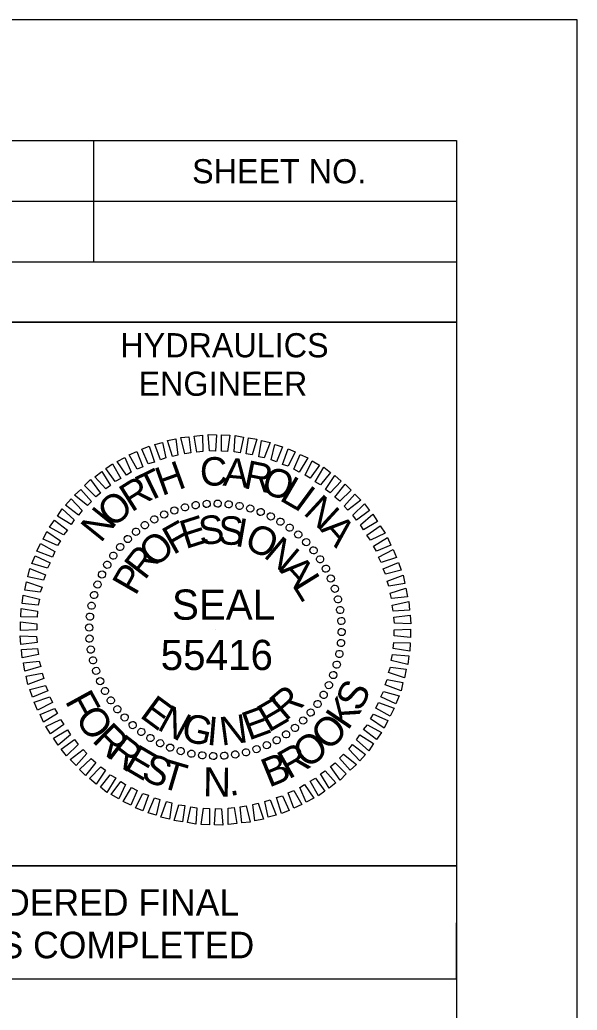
# Model space of a CAD drawing. Extents: x 573078 to 573156.2, y -55225.7 to -55195.8.
# Drawn here: x 573109.707 to 573112.014, y -55203.398 to -55199.298 of the extents above; entities that cross this region are included whole.
import ezdxf

# ---------------------------------------------------------------- set-up
doc = ezdxf.new("R2010")
doc.units = 0
for name, color, linetype in [('Prop Dimension', 7, 'Continuous'), ('Scratch_Level_0', 7, 'Continuous'), ('Scratch_Level_1', 7, 'Continuous'), ('Sheet Plan CELL', 7, 'Continuous'), ('Sheet Plot Border Inside CELL', 7, 'Continuous'), ('Sheet Sticker Exception Certification CELL', 7, 'Continuous')]:
    doc.layers.add(name, color=color, linetype=linetype)

msp = doc.modelspace()

# ---------------------------------------------------------------- linework, layer by layer
at = {"layer": 'Prop Dimension'}
for p, q in [((573110.39, -55201.316), (573110.39, -55201.316)), ((573110.4359, -55201.3077), (573110.4359, -55201.3077)), ((573110.4805, -55201.3015), (573110.4805, -55201.3015)), ((573110.5263, -55201.3005), (573110.5263, -55201.3005)), ((573110.5722, -55201.3035), (573110.5722, -55201.3035)), ((573110.617, -55201.3109), (573110.617, -55201.3109)), ((573110.6608, -55201.3202), (573110.6608, -55201.3202)), ((573110.3046, -55201.3452), (573110.3046, -55201.3452)), ((573110.3463, -55201.3285), (573110.3463, -55201.3285)), ((573110.7045, -55201.3348), (573110.7045, -55201.3348)), ((573110.7462, -55201.3535), (573110.7462, -55201.3535)), ((573110.2243, -55201.3901), (573110.2243, -55201.3901)), ((573110.2639, -55201.366), (573110.2639, -55201.366)), ((573110.7867, -55201.3744), (573110.7867, -55201.3744)), ((573110.8242, -55201.4005), (573110.8242, -55201.4005)), ((573110.188, -55201.416), (573110.188, -55201.416)), ((573110.8607, -55201.4285), (573110.8607, -55201.4285)), ((573110.1223, -55201.4796), (573110.1223, -55201.4796)), ((573110.1535, -55201.4473), (573110.1535, -55201.4473)), ((573110.8929, -55201.4597), (573110.8929, -55201.4597)), ((573110.0943, -55201.516), (573110.0943, -55201.516)), ((573110.9241, -55201.4942), (573110.9241, -55201.4942)), ((573110.0681, -55201.5535), (573110.0681, -55201.5535)), ((573110.9503, -55201.5306), (573110.9503, -55201.5306)), ((573110.0473, -55201.5942), (573110.0473, -55201.5942)), ((573110.9741, -55201.5701), (573110.9741, -55201.5701)), ((573110.0286, -55201.6359), (573110.0286, -55201.6359)), ((573110.995, -55201.6109), (573110.995, -55201.6109)), ((573110.014, -55201.6796), (573110.014, -55201.6796)), ((573111.0116, -55201.6525), (573111.0116, -55201.6525)), ((573110.0047, -55201.7233), (573110.0047, -55201.7233)), ((573111.0241, -55201.6963), (573111.0241, -55201.6963)), ((573109.9973, -55201.768), (573109.9973, -55201.768)), ((573111.0324, -55201.7421), (573111.0324, -55201.7421)), ((573111.0387, -55201.7867), (573111.0387, -55201.7867)), ((573109.9943, -55201.8138), (573109.9943, -55201.8138)), ((573111.0398, -55201.8326), (573111.0398, -55201.8326)), ((573109.9952, -55201.8596), (573109.9952, -55201.8596)), ((573111.0366, -55201.8784), (573111.0366, -55201.8784)), ((573110.0015, -55201.9045), (573110.0015, -55201.9045)), ((573111.0294, -55201.9233), (573111.0294, -55201.9233)), ((573110.0098, -55201.9504), (573110.0098, -55201.9504)), ((573111.0199, -55201.967), (573111.0199, -55201.967)), ((573110.0223, -55201.9941), (573110.0223, -55201.9941)), ((573111.0054, -55202.0108), (573111.0054, -55202.0108)), ((573110.039, -55202.0357), (573110.039, -55202.0357)), ((573110.9866, -55202.0524), (573110.9866, -55202.0524)), ((573110.0598, -55202.0762), (573110.0598, -55202.0762)), ((573110.9658, -55202.0929), (573110.9658, -55202.0929)), ((573110.0839, -55202.1158), (573110.0839, -55202.1158)), ((573110.9399, -55202.1304), (573110.9399, -55202.1304)), ((573110.1098, -55202.1524), (573110.1098, -55202.1524)), ((573110.9116, -55202.167), (573110.9116, -55202.167)), ((573110.141, -55202.1866), (573110.141, -55202.1866)), ((573110.1734, -55202.2179), (573110.1734, -55202.2179)), ((573110.8804, -55202.1991), (573110.8804, -55202.1991)), ((573110.2098, -55202.2461), (573110.2098, -55202.2461)), ((573110.8096, -55202.2565), (573110.8096, -55202.2565)), ((573110.8462, -55202.2304), (573110.8462, -55202.2304)), ((573110.2472, -55202.272), (573110.2472, -55202.272)), ((573110.288, -55202.2929), (573110.288, -55202.2929)), ((573110.7295, -55202.3012), (573110.7295, -55202.3012)), ((573110.77, -55202.2804), (573110.77, -55202.2804)), ((573110.3296, -55202.3116), (573110.3296, -55202.3116)), ((573110.3734, -55202.3262), (573110.3734, -55202.3262)), ((573110.4171, -55202.3357), (573110.4171, -55202.3357)), ((573110.4618, -55202.3428), (573110.4618, -55202.3428)), ((573110.5534, -55202.3449), (573110.5534, -55202.3449)), ((573110.5983, -55202.3387), (573110.5983, -55202.3387)), ((573110.6441, -55202.3303), (573110.6441, -55202.3303)), ((573110.6879, -55202.3178), (573110.6879, -55202.3178)), ((573110.5076, -55202.3461), (573110.5076, -55202.3461))]:
    msp.add_line(p, q, dxfattribs=at)
for points in [[(573110.34, -55201.1057), (573110.3181, -55201.0402), (573110.3535, -55201.0328), (573110.3618, -55201.1006)], [(573110.39, -55201.0943), (573110.3734, -55201.0277), (573110.4076, -55201.0245), (573110.415, -55201.0911)], [(573110.44, -55201.0881), (573110.4284, -55201.0214), (573110.4639, -55201.0173), (573110.465, -55201.0849)], [(573110.4921, -55201.0828), (573110.4868, -55201.0152), (573110.5212, -55201.0161), (573110.5171, -55201.0839)], [(573110.5421, -55201.0839), (573110.5421, -55201.0161), (573110.5763, -55201.0173), (573110.5671, -55201.0848)], [(573110.5941, -55201.0869), (573110.5983, -55201.0194), (573110.6326, -55201.0256), (573110.6191, -55201.0911)], [(573110.6441, -55201.0953), (573110.6534, -55201.0286), (573110.6879, -55201.0339), (573110.6691, -55201.0985)], [(573110.2389, -55201.136), (573110.2118, -55201.0756), (573110.2431, -55201.0631), (573110.2651, -55201.1297)], [(573110.2901, -55201.1193), (573110.266, -55201.0568), (573110.2984, -55201.0474), (573110.3118, -55201.1119)], [(573110.6971, -55201.1068), (573110.7075, -55201.039), (573110.7429, -55201.0474), (573110.7191, -55201.1119)], [(573110.7471, -55201.1203), (573110.7628, -55201.0557), (573110.795, -55201.0661), (573110.7691, -55201.1277)], [(573110.7941, -55201.139), (573110.8179, -55201.0735), (573110.8471, -55201.086), (573110.8179, -55201.1464)], [(573110.1484, -55201.1827), (573110.1098, -55201.1265), (573110.1422, -55201.1098), (573110.1681, -55201.1702)], [(573110.1931, -55201.1577), (573110.1598, -55201.0994), (573110.1922, -55201.0849), (573110.216, -55201.1485)], [(573110.8408, -55201.1589), (573110.867, -55201.0974), (573110.8991, -55201.1119), (573110.8637, -55201.1702)], [(573110.1026, -55201.2089), (573110.064, -55201.1557), (573110.091, -55201.136), (573110.1255, -55201.1964)], [(573110.8887, -55201.1827), (573110.917, -55201.1235), (573110.9482, -55201.1411), (573110.9086, -55201.1952)], [(573110.9295, -55201.211), (573110.9658, -55201.1506), (573110.9929, -55201.1723), (573110.9524, -55201.2235)], [(573110.063, -55201.2401), (573110.0181, -55201.1901), (573110.0464, -55201.1682), (573110.0827, -55201.2265)], [(573110.972, -55201.2422), (573111.0107, -55201.1848), (573111.0378, -55201.2077), (573110.9919, -55201.2568)], [(573110.0214, -55201.2723), (573109.9756, -55201.2265), (573110.0006, -55201.2015), (573110.0411, -55201.2577)], [(573111.0116, -55201.2744), (573111.0544, -55201.2202), (573111.0794, -55201.2452), (573111.0315, -55201.2901)], [(573109.9869, -55201.3089), (573109.9339, -55201.2661), (573109.9598, -55201.2422), (573110.0036, -55201.2922)], [(573111.0491, -55201.3109), (573111.094, -55201.2619), (573111.119, -55201.2869), (573111.0648, -55201.3276)], [(573109.9506, -55201.3484), (573109.8964, -55201.3077), (573109.9193, -55201.2806), (573109.9651, -55201.3297)], [(573111.0857, -55201.3484), (573111.1336, -55201.3015), (573111.1553, -55201.3297), (573111.1003, -55201.3693)], [(573109.9193, -55201.388), (573109.8631, -55201.3526), (573109.8828, -55201.3223), (573109.9328, -55201.3681)], [(573111.1169, -55201.3889), (573111.1678, -55201.3452), (573111.1877, -55201.3755), (573111.1294, -55201.4088)], [(573109.8881, -55201.4297), (573109.8298, -55201.3984), (573109.8506, -55201.3693), (573109.9047, -55201.4109)], [(573111.144, -55201.4317), (573111.1991, -55201.3922), (573111.219, -55201.4234), (573111.1586, -55201.4526)], [(573109.8631, -55201.4743), (573109.8036, -55201.4484), (573109.8194, -55201.416), (573109.8756, -55201.4547)], [(573111.1711, -55201.4776), (573111.2294, -55201.441), (573111.2428, -55201.4734), (573111.1836, -55201.4972)], [(573109.8423, -55201.5222), (573109.7777, -55201.4984), (573109.7932, -55201.466), (573109.8527, -55201.4993)], [(573109.8214, -55201.5681), (573109.7569, -55201.5493), (573109.7703, -55201.5171), (573109.8328, -55201.5463)], [(573111.1919, -55201.5222), (573111.2532, -55201.491), (573111.2669, -55201.5243), (573111.2023, -55201.5451)], [(573111.2106, -55201.5713), (573111.274, -55201.5442), (573111.2856, -55201.5764), (573111.221, -55201.593)], [(573109.8057, -55201.618), (573109.7411, -55201.6046), (573109.7485, -55201.5701), (573109.814, -55201.5963)], [(573111.2273, -55201.6213), (573111.2939, -55201.5972), (573111.3002, -55201.6317), (573111.2345, -55201.643)], [(573109.7923, -55201.668), (573109.7277, -55201.6597), (573109.7349, -55201.6243), (573109.8006, -55201.6463)], [(573109.784, -55201.7213), (573109.7173, -55201.715), (573109.7215, -55201.6796), (573109.789, -55201.6963)], [(573111.2398, -55201.6713), (573111.3053, -55201.6514), (573111.3115, -55201.6868), (573111.246, -55201.693)], [(573111.249, -55201.7212), (573111.3169, -55201.7067), (573111.3199, -55201.7421), (573111.2532, -55201.7462)], [(573109.7786, -55201.7712), (573109.7111, -55201.7692), (573109.7131, -55201.7347), (573109.7807, -55201.7462)], [(573111.2553, -55201.7712), (573111.3231, -55201.7629), (573111.3252, -55201.7983), (573111.2574, -55201.7962)], [(573109.7777, -55201.8233), (573109.7099, -55201.8263), (573109.7099, -55201.7909), (573109.7777, -55201.7983)], [(573109.7786, -55201.8754), (573109.7111, -55201.8837), (573109.709, -55201.8483), (573109.7765, -55201.8504)], [(573111.2565, -55201.8233), (573111.324, -55201.8201), (573111.324, -55201.8555), (573111.2565, -55201.8483)], [(573111.2553, -55201.8754), (573111.3231, -55201.8775), (573111.321, -55201.9117), (573111.2532, -55201.9004)], [(573109.7849, -55201.9254), (573109.7173, -55201.9399), (573109.7141, -55201.9045), (573109.7807, -55201.9004)], [(573111.2502, -55201.9254), (573111.3169, -55201.9316), (573111.3127, -55201.967), (573111.2449, -55201.9504)], [(573109.7944, -55201.9753), (573109.7286, -55201.995), (573109.7224, -55201.9596), (573109.7881, -55201.9534)], [(573109.8069, -55202.0253), (573109.7402, -55202.0492), (573109.734, -55202.0149), (573109.7995, -55202.0033)], [(573111.2419, -55201.9784), (573111.3064, -55201.9867), (573111.299, -55202.0221), (573111.2335, -55202.0003)], [(573109.8235, -55202.0753), (573109.7599, -55202.1024), (573109.7485, -55202.07), (573109.8131, -55202.0533)], [(573111.2282, -55202.0283), (573111.2928, -55202.042), (573111.2856, -55202.0762), (573111.2199, -55202.0503)], [(573111.2127, -55202.0783), (573111.2773, -55202.0971), (573111.2636, -55202.1295), (573111.2011, -55202.1003)], [(573109.8423, -55202.1241), (573109.7807, -55202.1554), (573109.7673, -55202.1221), (573109.8319, -55202.1012)], [(573111.1919, -55202.1241), (573111.2565, -55202.1482), (573111.2407, -55202.1804), (573111.1815, -55202.1471)], [(573109.8631, -55202.169), (573109.8048, -55202.2054), (573109.7911, -55202.1732), (573109.8506, -55202.1491)], [(573111.1711, -55202.172), (573111.2303, -55202.1982), (573111.2148, -55202.2304), (573111.1586, -55202.192)], [(573109.8902, -55202.2149), (573109.8349, -55202.2544), (573109.8152, -55202.2232), (573109.8756, -55202.194)], [(573111.1461, -55202.2169), (573111.2044, -55202.2482), (573111.1836, -55202.2773), (573111.1294, -55202.2357)], [(573109.9172, -55202.2574), (573109.8661, -55202.3012), (573109.8464, -55202.2711), (573109.9047, -55202.2378)], [(573111.1148, -55202.2586), (573111.1711, -55202.294), (573111.1512, -55202.3241), (573111.1012, -55202.2783)], [(573109.9485, -55202.2982), (573109.9006, -55202.3449), (573109.8786, -55202.3169), (573109.9339, -55202.2773)], [(573111.0836, -55202.2982), (573111.1377, -55202.3387), (573111.1148, -55202.3657), (573111.069, -55202.3169)], [(573109.9848, -55202.3357), (573109.9402, -55202.3845), (573109.9152, -55202.3595), (573109.9693, -55202.319)], [(573111.047, -55202.3377), (573111.1003, -55202.3803), (573111.0741, -55202.4044), (573111.0304, -55202.3544)], [(573110.0223, -55202.372), (573109.9797, -55202.4261), (573109.9547, -55202.4012), (573110.0026, -55202.3565)], [(573111.0128, -55202.3741), (573111.0586, -55202.4199), (573111.0336, -55202.4449), (573110.9929, -55202.3887)], [(573110.0619, -55202.4044), (573110.0235, -55202.4616), (573109.9964, -55202.4386), (573110.0422, -55202.3898)], [(573110.1047, -55202.4356), (573110.0681, -55202.496), (573110.0411, -55202.474), (573110.0818, -55202.4231)], [(573110.9711, -55202.4065), (573111.0158, -55202.4565), (573110.9878, -55202.4782), (573110.9512, -55202.4199)], [(573110.1452, -55202.4636), (573110.1172, -55202.5231), (573110.0859, -55202.5053), (573110.1255, -55202.4511)], [(573110.8857, -55202.4636), (573110.9241, -55202.5199), (573110.892, -55202.5365), (573110.8658, -55202.4761)], [(573110.9315, -55202.4377), (573110.97, -55202.4907), (573110.9429, -55202.5106), (573110.9086, -55202.4502)], [(573110.1931, -55202.4877), (573110.1672, -55202.549), (573110.1348, -55202.5345), (573110.1702, -55202.4761)], [(573110.2401, -55202.5074), (573110.216, -55202.5731), (573110.1868, -55202.5606), (573110.216, -55202.5002)], [(573110.8408, -55202.4886), (573110.8742, -55202.5469), (573110.842, -55202.5615), (573110.8179, -55202.4981)], [(573110.2868, -55202.5261), (573110.2713, -55202.5907), (573110.2389, -55202.5803), (573110.2651, -55202.5189)], [(573110.3368, -55202.5398), (573110.3264, -55202.6073), (573110.291, -55202.599), (573110.3151, -55202.5345)], [(573110.39, -55202.5511), (573110.3805, -55202.6178), (573110.3463, -55202.6127), (573110.365, -55202.5481)], [(573110.6941, -55202.5407), (573110.7159, -55202.6064), (573110.6805, -55202.6136), (573110.6721, -55202.546)], [(573110.7441, -55202.5273), (573110.7679, -55202.5898), (573110.7358, -55202.599), (573110.7221, -55202.5344)], [(573110.795, -55202.5106), (573110.8221, -55202.571), (573110.7908, -55202.5835), (573110.7691, -55202.5169)], [(573110.44, -55202.5594), (573110.4359, -55202.6272), (573110.4014, -55202.621), (573110.415, -55202.5553)], [(573110.4921, -55202.5627), (573110.4921, -55202.6303), (573110.4576, -55202.6293), (573110.4671, -55202.5615)], [(573110.5421, -55202.5636), (573110.5472, -55202.6314), (573110.5129, -55202.6303), (573110.5171, -55202.5627)], [(573110.5941, -55202.5585), (573110.6055, -55202.6252), (573110.5701, -55202.6293), (573110.5691, -55202.5615)], [(573110.6441, -55202.5523), (573110.6608, -55202.6189), (573110.6263, -55202.6219), (573110.6191, -55202.5553)]]:
    msp.add_lwpolyline(points, close=True, dxfattribs=at)
for centre, major_axis in [((573110.347, -55201.3293), (-0.0049, 0.0142)), ((573110.3907, -55201.3164), (-0.0036, 0.0146)), ((573110.4354, -55201.3073), (-0.0023, 0.0148)), ((573110.4807, -55201.3022), (-0.001, 0.015)), ((573110.5262, -55201.301), (0.0003, 0.015)), ((573110.5717, -55201.3037), (0.0016, 0.0149)), ((573110.6168, -55201.3105), (0.0029, 0.0147)), ((573110.6611, -55201.3211), (0.0041, 0.0144)), ((573110.7043, -55201.3356), (0.0054, 0.014)), ((573110.2638, -55201.3664), (-0.0073, 0.0131)), ((573110.3046, -55201.346), (-0.0061, 0.0137)), ((573110.7461, -55201.3538), (0.0066, 0.0135)), ((573110.7861, -55201.3755), (0.0077, 0.0129)), ((573110.1884, -55201.4173), (-0.0094, 0.0117)), ((573110.225, -55201.3902), (-0.0084, 0.0124)), ((573110.8241, -55201.4006), (0.0088, 0.0121)), ((573110.1542, -55201.4475), (-0.0104, 0.0108)), ((573110.8598, -55201.429), (0.0098, 0.0113)), ((573110.1229, -55201.4805), (-0.0113, 0.0098)), ((573110.8928, -55201.4604), (0.0108, 0.0104)), ((573110.923, -55201.4945), (0.0117, 0.0094)), ((573110.0945, -55201.5162), (-0.0121, 0.0088)), ((573110.9501, -55201.5311), (0.0124, 0.0084)), ((573110.0693, -55201.5542), (-0.0129, 0.0077)), ((573110.974, -55201.57), (0.0131, 0.0073)), ((573110.0476, -55201.5943), (-0.0135, 0.0066)), ((573110.9943, -55201.6108), (0.0137, 0.0061)), ((573110.0294, -55201.636), (-0.014, 0.0054)), ((573111.011, -55201.6532), (0.0142, 0.0049)), ((573110.015, -55201.6793), (-0.0144, 0.0041)), ((573111.0239, -55201.6969), (0.0146, 0.0036)), ((573110.0043, -55201.7236), (-0.0147, 0.0029)), ((573111.033, -55201.7415), (0.0148, 0.0023)), ((573109.9976, -55201.7686), (-0.0149, 0.0016)), ((573109.9948, -55201.8141), (-0.015, 0.0003)), ((573111.0382, -55201.7868), (0.015, 0.001)), ((573109.996, -55201.8597), (-0.015, -0.001)), ((573111.0394, -55201.8324), (0.015, -0.0003)), ((573110.0012, -55201.905), (-0.0148, -0.0023)), ((573111.0366, -55201.8778), (0.0149, -0.0016)), ((573110.0103, -55201.9496), (-0.0146, -0.0036)), ((573111.0298, -55201.9229), (0.0147, -0.0029)), ((573111.0192, -55201.9672), (0.0144, -0.0041)), ((573110.0232, -55201.9933), (-0.0142, -0.0049)), ((573111.0047, -55202.0104), (0.014, -0.0054)), ((573110.0399, -55202.0357), (-0.0137, -0.0061)), ((573110.9866, -55202.0522), (0.0135, -0.0066)), ((573110.0602, -55202.0765), (-0.0131, -0.0073)), ((573110.084, -55202.1153), (-0.0124, -0.0084)), ((573110.9648, -55202.0923), (0.0129, -0.0077)), ((573110.1111, -55202.152), (-0.0117, -0.0094)), ((573110.9397, -55202.1303), (0.0121, -0.0088)), ((573110.1413, -55202.1861), (-0.0108, -0.0104)), ((573110.9113, -55202.1659), (0.0113, -0.0098)), ((573110.1744, -55202.2175), (-0.0098, -0.0113)), ((573110.8458, -55202.2292), (0.0094, -0.0117)), ((573110.8799, -55202.199), (0.0104, -0.0108)), ((573110.2101, -55202.2458), (-0.0088, -0.0121)), ((573110.2481, -55202.271), (-0.0077, -0.0129)), ((573110.7703, -55202.2801), (0.0073, -0.0131)), ((573110.8092, -55202.2563), (0.0084, -0.0124)), ((573110.2881, -55202.2927), (-0.0066, -0.0135)), ((573110.3299, -55202.3109), (-0.0054, -0.014)), ((573110.6872, -55202.3171), (0.0049, -0.0142)), ((573110.7296, -55202.3004), (0.0061, -0.0137)), ((573110.3731, -55202.3254), (-0.0041, -0.0144)), ((573110.4174, -55202.336), (-0.0029, -0.0147)), ((573110.4625, -55202.3427), (-0.0016, -0.0149)), ((573110.508, -55202.3455), (-0.0003, -0.015)), ((573110.5535, -55202.3443), (0.001, -0.015)), ((573110.5988, -55202.3392), (0.0023, -0.0148)), ((573110.6435, -55202.3301), (0.0036, -0.0146))]:
    msp.add_ellipse(centre, major_axis=major_axis, ratio=0.999708, dxfattribs=at)
at = {"layer": 'Scratch_Level_0'}
msp.add_line((573110.5171, -55201.8233), (573110.5171, -55201.8233), dxfattribs=at)
at = {"layer": 'Scratch_Level_1'}
msp.add_line((573110.5171, -55201.8233), (573110.5171, -55201.8233), dxfattribs=at)
at = {"layer": 'Sheet Plan CELL'}
for p, q in [((573110.0144, -55200.2999), (573110.0144, -55199.7984)), ((573107.5132, -55200.0494), (573111.5142, -55200.0497)), ((573107.5132, -55200.3002), (573111.5142, -55200.2997))]:
    msp.add_line(p, q, dxfattribs=at)
for points in [[(573081.5142, -55199.7984), (573111.5142, -55199.7984), (573111.5142, -55220.7984), (573081.5142, -55220.7984)], [(573107.5132, -55199.7984), (573111.5142, -55199.7984), (573111.5142, -55200.5499), (573107.5132, -55200.5499)], [(573109.5142, -55200.5499), (573111.5142, -55200.5499), (573111.5142, -55202.7999), (573109.5142, -55202.7999)]]:
    msp.add_lwpolyline(points, close=True, dxfattribs=at)
at = {"layer": 'Sheet Plot Border Inside CELL'}
msp.add_lwpolyline([(573112.0142, -55199.2984), (573078.0142, -55199.2984), (573078.0142, -55221.2984), (573112.0142, -55221.2984)], close=True, dxfattribs=at)
at = {"layer": 'Sheet Sticker Exception Certification CELL'}
for p, q in [((573107.5132, -55202.7999), (573111.5142, -55202.7999)), ((573111.5142, -55202.7999), (573111.5139, -55203.2702)), ((573111.5139, -55203.2699), (573107.5132, -55203.2699))]:
    msp.add_line(p, q, dxfattribs=at)

# ---------------------------------------------------------------- texts
at = {"layer": 'Prop Dimension'}
for s, height, rotation, p in [('C', 0.1177, 1.0718, (573110.4537, -55201.2274)), ('A', 0.1177, 354.8222, (573110.5453, -55201.2262)), ('T', 0.1177, 26.0703, (573110.232, -55201.2991)), ('H', 0.1177, 19.8207, (573110.2954, -55201.27)), ('R', 0.1177, 348.5725, (573110.6286, -55201.2357)), ('O', 0.1177, 342.3229, (573110.7015, -55201.2545)), ('R', 0.1177, 32.3199, (573110.1695, -55201.3387)), ('L', 0.1177, 329.8237, (573110.7777, -55201.2846)), ('I', 0.1177, 323.5741, (573110.836, -55201.3149)), ('O', 0.1177, 38.5695, (573110.0892, -55201.4044)), ('N', 0.1177, 317.3244, (573110.8765, -55201.342)), ('N', 0.1177, 51.0688, (573110.0424, -55201.4669)), ('E', 0.1177, 17.6709, (573110.3933, -55201.4898)), ('S', 0.1177, 6.1833, (573110.4537, -55201.4732)), ('S', 0.1177, 358.4778, (573110.5277, -55201.4699)), ('F', 0.1177, 29.3, (573110.3424, -55201.5148)), ('I', 0.1177, 350.0931, (573110.5944, -55201.4753)), ('O', 0.1177, 335.3611, (573110.6307, -55201.4824)), ('A', 0.1177, 311.0748, (573110.9484, -55201.4095)), ('O', 0.1177, 43.5875, (573110.2683, -55201.5711)), ('N', 0.1177, 319.95, (573110.7119, -55201.519)), ('R', 0.1177, 52.4166, (573110.2246, -55201.621)), ('P', 0.1177, 60.1222, (573110.1862, -55201.6856)), ('A', 0.1177, 312.2445, (573110.7807, -55201.5803)), ('L', 0.1177, 301.6752, (573110.8327, -55201.6386)), ('SEAL', 0.12497, 360, (573110.337, -55201.7814)), ('55416', 0.12497, 360, (573110.2903, -55201.9897)), ('S', 0.12, 63.6332, (573111.1164, -55202.1665)), ('F', 0.12, 298.6676, (573109.8924, -55202.1178)), ('E', 0.1177, 323.6798, (573110.1996, -55202.1822)), ('R', 0.1177, 40.7353, (573110.8068, -55202.2042)), ('K', 0.12, 55.9775, (573111.0653, -55202.2433)), ('N', 0.1177, 331.3854, (573110.2715, -55202.2334)), ('E', 0.1177, 20.0411, (573110.6548, -55202.2822)), ('E', 0.1177, 30.1214, (573110.7369, -55202.25)), ('O', 0.12, 305.5335, (573109.9321, -55202.1903)), ('G', 0.1177, 346.7965, (573110.3704, -55202.2792)), ('N', 0.1177, 7.7341, (573110.5423, -55202.303)), ('O', 0.12, 46.28, (573110.9868, -55202.3296)), ('R', 0.12, 315.231, (573110.0023, -55202.2836)), ('I', 0.1177, 355.0405, (573110.4787, -55202.2989)), ('R', 0.12, 322.3858, (573110.0636, -55202.3442)), ('O', 0.12, 36.5825, (573110.8948, -55202.4015)), ('E', 0.12, 329.5406, (573110.132, -55202.3966)), ('R', 0.12, 29.4277, (573110.8198, -55202.444)), ('S', 0.12, 336.4643, (573110.2039, -55202.4388)), ('B', 0.12, 22.1381, (573110.7386, -55202.4774)), ('T', 0.12, 343.5228, (573110.2819, -55202.4727)), ('N', 0.12, 359.1037, (573110.465, -55202.512)), ('.', 0.12, 8.2811, (573110.5755, -55202.5114))]:
    msp.add_text(s, height=height, rotation=rotation, dxfattribs=at).set_placement(p)
at = {"layer": 'Sheet Plan CELL'}
for s, p in [('SHEET NO.', (573110.4204, -55199.9752)), ('HYDRAULICS', (573110.1234, -55200.6954)), ('ENGINEER', (573110.1987, -55200.8547))]:
    msp.add_text(s, height=0.1, rotation=0, dxfattribs=at).set_placement(p)
at = {"layer": 'Sheet Sticker Exception Certification CELL'}
for s, p in [('DOCUMENT NOT CONSIDERED FINAL', (573107.9346, -55203.0068)), ('UNLESS ALL SIGNATURES COMPLETED', (573107.8332, -55203.1828))]:
    msp.add_text(s, height=0.11, dxfattribs=at).set_placement(p)

doc.saveas('drawing.dxf')
